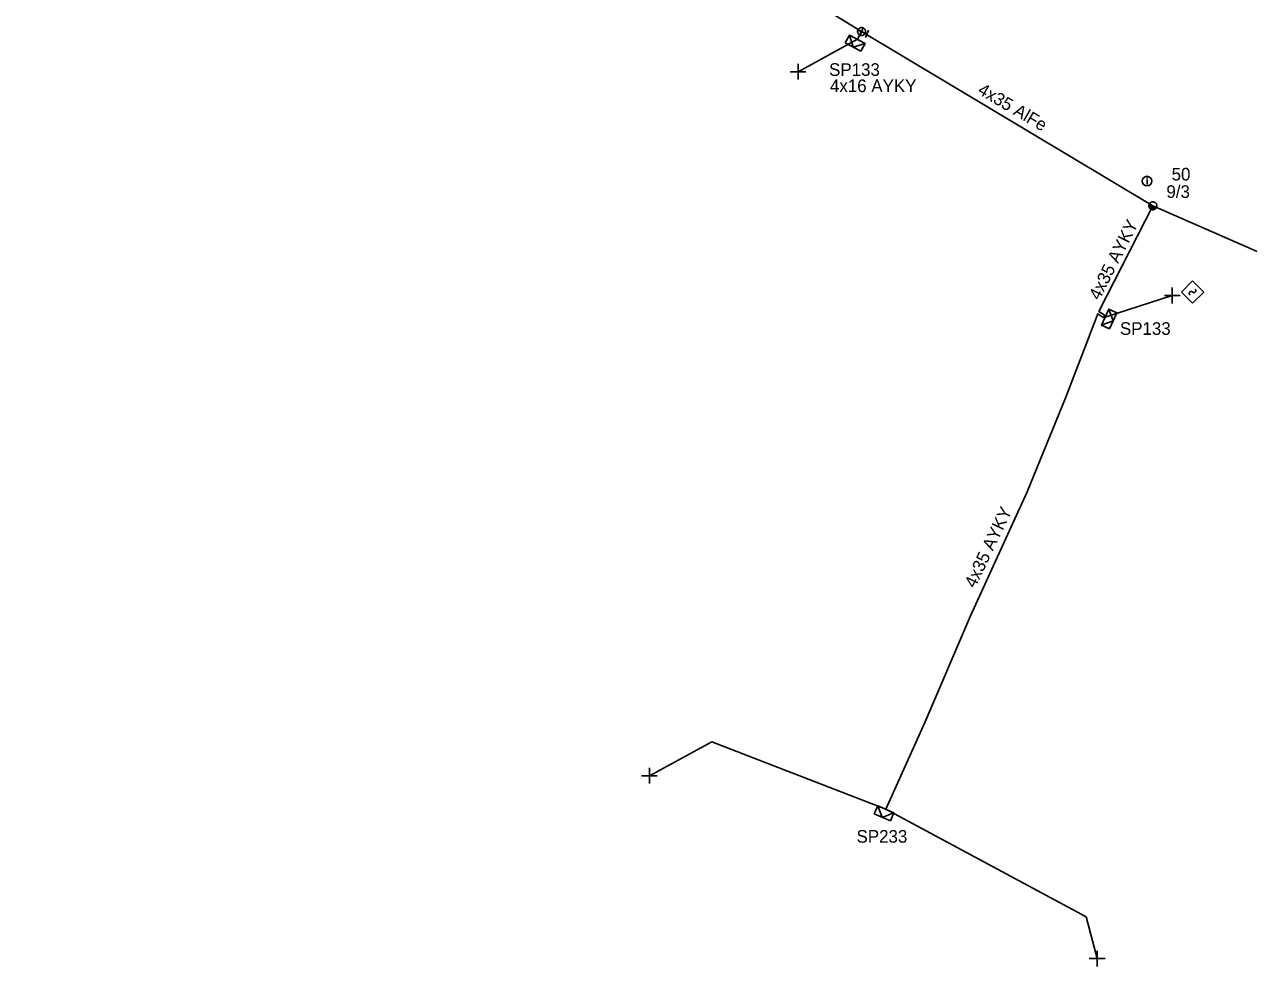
# Model space of a CAD drawing. Extents: x -748492 to -735633, y -1146251 to -1139940.
# Drawn here: x -736671.1 to -736574.3, y -1143545.2 to -1143470.7 of the extents above; entities that cross this region are included whole.
import ezdxf

# ---------------------------------------------------------------- set-up
doc = ezdxf.new("R2010")
doc.units = 0
for name, color, linetype in [('Vrstva 1', 7, 'Continuous'), ('Vrstva 10', 7, 'Continuous'), ('Vrstva 12', 7, 'Continuous'), ('Vrstva 13', 7, 'Continuous'), ('Vrstva 14', 7, 'Continuous'), ('Vrstva 2', 7, 'Continuous'), ('Vrstva 31', 7, 'Continuous'), ('Vrstva 33', 7, 'Continuous'), ('Vrstva 34', 7, 'Continuous'), ('Vrstva 36', 7, 'Continuous'), ('Vrstva 5', 7, 'Continuous'), ('Vrstva 52', 7, 'Continuous'), ('Vrstva 54', 7, 'Continuous'), ('Vrstva 59', 7, 'Continuous'), ('Vrstva 6', 7, 'Continuous'), ('Vrstva 9', 7, 'Continuous')]:
    doc.layers.add(name, color=color, linetype=linetype)

# ---------------------------------------------------------------- blocks, each defined once
blk = doc.blocks.new('NN440')
at = {"layer": 'Vrstva 2'}
for points in [[(0.63, 0), (0.63, 0.06), (0.62, 0.13), (0.6, 0.19), (0.58, 0.25), (0.55, 0.31), (0.51, 0.37), (0.47, 0.42), (0.42, 0.46), (0.37, 0.51), (0.32, 0.54), (0.26, 0.57), (0.2, 0.59), (0.13, 0.61), (0.07, 0.62), (0, 0.63), (-0.06, 0.62), (-0.13, 0.61), (-0.19, 0.59), (-0.26, 0.57), (-0.31, 0.54), (-0.37, 0.51), (-0.42, 0.46), (-0.47, 0.42), (-0.51, 0.37), (-0.54, 0.31), (-0.57, 0.25), (-0.6, 0.19), (-0.62, 0.13), (-0.63, 0.06), (-0.63, 0), (-0.63, -0.07), (-0.62, -0.14), (-0.6, -0.2), (-0.57, -0.26), (-0.54, -0.32), (-0.51, -0.37), (-0.47, -0.43), (-0.42, -0.47), (-0.37, -0.51), (-0.31, -0.55), (-0.26, -0.58), (-0.19, -0.6), (-0.13, -0.62), (-0.06, -0.63), (0, -0.63), (0.07, -0.63), (0.13, -0.62), (0.2, -0.6), (0.26, -0.58), (0.32, -0.55), (0.37, -0.51), (0.42, -0.47), (0.47, -0.43), (0.51, -0.37), (0.55, -0.32), (0.58, -0.26), (0.6, -0.2), (0.62, -0.14), (0.63, -0.07), (0.63, 0)], [(-0.63, 0), (0.63, 0)], [(-0.6, -0.18), (0.57, -0.18)], [(-0.51, -0.32), (0.5, -0.32)], [(-0.37, -0.47), (0.35, -0.47)]]:
    blk.add_lwpolyline(points, dxfattribs=at)
blk = doc.blocks.new('NN770')
at = {"layer": 'Vrstva 10'}
for p, q in [((0.002, 0.187), (0.002, 0.263)), ((0.002, -0.276), (0.002, 0.111))]:
    blk.add_line(p, q, dxfattribs=at)
blk.add_circle((0, -0.008), 0.375, dxfattribs=at)
blk = doc.blocks.new('NN800')
at = {"layer": 'Vrstva 1'}
for points in [[(-0.442, 0.442), (0.442, -0.442)], [(-0.442, -0.442), (0.442, 0.442)]]:
    blk.add_lwpolyline(points, dxfattribs=at)
blk = doc.blocks.new('NN630')
at = {"layer": 'Vrstva 9'}
for points in [[(-0.003, -0.7), (-0.703, 0)], [(-0.703, -0.7), (-0.703, 0), (0.697, 0), (0.697, -0.7)], [(-0.703, -0.7), (0.697, -0.7)], [(-0.003, -0.7), (0.697, 0)]]:
    blk.add_lwpolyline(points, dxfattribs=at)
blk = doc.blocks.new('NN740')
at = {"layer": 'Vrstva 1'}
for points in [[(0.624, 0.624), (-0.626, 0.624)], [(-0.626, 0.624), (-0.626, -0.626)], [(-0.001, -0.001), (-0.002, 0.015), (-0.004, 0.031), (-0.008, 0.046), (-0.014, 0.061), (-0.021, 0.075), (-0.03, 0.089), (-0.04, 0.101), (-0.051, 0.112), (-0.063, 0.123), (-0.077, 0.131), (-0.091, 0.139), (-0.106, 0.145), (-0.121, 0.149), (-0.137, 0.151), (-0.153, 0.152), (-0.169, 0.151), (-0.185, 0.149), (-0.2, 0.145), (-0.215, 0.139), (-0.229, 0.132), (-0.243, 0.123), (-0.255, 0.113), (-0.266, 0.102), (-0.276, 0.09), (-0.285, 0.076), (-0.293, 0.062), (-0.298, 0.047), (-0.303, 0.032), (-0.305, 0.016), (-0.306, 0), (-0.306, -0.001)], [(0.624, -0.626), (0.624, 0.624)], [(-0.626, -0.626), (0.624, -0.626)], [(-0.001, -0.001), (0, -0.017), (0.002, -0.032), (0.006, -0.048), (0.011, -0.062), (0.018, -0.077), (0.026, -0.09), (0.036, -0.102), (0.047, -0.114), (0.059, -0.124), (0.072, -0.133), (0.085, -0.14), (0.1, -0.146), (0.115, -0.15), (0.131, -0.153), (0.146, -0.154), (0.162, -0.154), (0.178, -0.151), (0.193, -0.148), (0.208, -0.142), (0.222, -0.135), (0.235, -0.127), (0.247, -0.118), (0.259, -0.107), (0.269, -0.095), (0.278, -0.082), (0.285, -0.068), (0.291, -0.053), (0.295, -0.038), (0.298, -0.023), (0.299, -0.007), (0.299, -0.006)]]:
    blk.add_lwpolyline(points, dxfattribs=at)
blk = doc.blocks.new('NN410')
at = {"layer": 'Vrstva 2'}
for points in [[(0.01, 0.63), (-0.06, 0.63), (-0.13, 0.62), (-0.19, 0.6), (-0.25, 0.58), (-0.31, 0.55), (-0.37, 0.51), (-0.42, 0.47), (-0.46, 0.42), (-0.5, 0.37), (-0.54, 0.32), (-0.57, 0.26), (-0.59, 0.2), (-0.61, 0.13), (-0.62, 0.07), (-0.62, 0), (-0.62, -0.06), (-0.61, -0.13), (-0.59, -0.19), (-0.57, -0.25), (-0.54, -0.31), (-0.5, -0.37), (-0.46, -0.42), (-0.42, -0.47), (-0.37, -0.51), (-0.31, -0.54), (-0.25, -0.57), (-0.19, -0.6), (-0.13, -0.61), (-0.06, -0.62), (0.01, -0.63), (0.07, -0.62), (0.14, -0.61), (0.2, -0.6), (0.26, -0.57), (0.32, -0.54), (0.38, -0.51), (0.43, -0.47), (0.47, -0.42), (0.51, -0.37), (0.55, -0.31), (0.58, -0.25), (0.6, -0.19), (0.62, -0.13), (0.63, -0.06), (0.63, 0), (0.63, 0.07), (0.62, 0.13), (0.6, 0.2), (0.58, 0.26), (0.55, 0.32), (0.51, 0.37), (0.47, 0.42), (0.43, 0.47), (0.38, 0.51), (0.32, 0.55), (0.26, 0.58), (0.2, 0.6), (0.14, 0.62), (0.07, 0.63), (0.01, 0.63)], [(0, -0.63), (0, 0.63)], [(0.96, -0.63), (0.96, 0.63)], [(-0.63, 0), (0.63, 0)]]:
    blk.add_lwpolyline(points, dxfattribs=at)

msp = doc.modelspace()

# ---------------------------------------------------------------- linework, layer by layer
at = {"layer": 'Vrstva 1'}
for points in [[(-736676.261, -1143404.169), (-736662.23, -1143427.97), (-736645.42, -1143442.01), (-736626.46, -1143458.019), (-736604.89, -1143471.26), (-736581.85, -1143485.04)], [(-736581.85, -1143485.04), (-736559.03, -1143495.02), (-736543, -1143503.11), (-736522.07, -1143513.24)]]:
    msp.add_lwpolyline(points, dxfattribs=at)
at = {"layer": 'Vrstva 5'}
msp.add_lwpolyline([(-736581.85, -1143485.04), (-736586.114, -1143493.39), (-736585.706, -1143493.663), (-736585.62, -1143493.84)], dxfattribs=at)
at = {"layer": 'Vrstva 52'}
for points in [[(-736604.89, -1143471.26), (-736605.221, -1143471.872)], [(-736585.62, -1143493.84), (-736585.808, -1143493.835), (-736586.197, -1143493.576), (-736588.74, -1143500.17), (-736591.79, -1143507.66), (-736596.28, -1143517.47), (-736599.88, -1143525.89), (-736602.96, -1143532.76)]]:
    msp.add_lwpolyline(points, dxfattribs=at)
at = {"layer": 'Vrstva 59'}
for points in [[(-736605.221, -1143471.872), (-736609.912, -1143474.433)], [(-736585.62, -1143493.84), (-736580.314, -1143492.136)], [(-736602.96, -1143532.76), (-736616.74, -1143527.413), (-736621.667, -1143530.104)], [(-736602.96, -1143532.76), (-736587.137, -1143541.269), (-736586.251, -1143544.567)]]:
    msp.add_lwpolyline(points, dxfattribs=at)

# ---------------------------------------------------------------- block references
at = {"layer": 'Vrstva 13'}
for name, p, xscale, yscale, rotation in [('NN410', (-736604.89, -1143471.26), 0.49999999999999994, 0.5000000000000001, -21.950945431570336), ('NN440', (-736581.85, -1143485.04), 0.5000000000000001, 0.4999999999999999, -22.701708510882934)]:
    msp.add_blockref(name, p, dxfattribs=dict(at, xscale=xscale, yscale=yscale, rotation=rotation))
at = {"layer": 'Vrstva 31'}
for p, rotation in [((-736605.221, -1143471.872), -28.231918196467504), ((-736585.62, -1143493.84), 65.75311860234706), ((-736602.96, -1143532.76), -24.06667780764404)]:
    msp.add_blockref('NN630', p, dxfattribs=dict(at, rotation=rotation))
at = {"layer": 'Vrstva 34'}
for name, p, rotation in [('NN800', (-736609.912, -1143474.433), 45), ('NN740', (-736578.712, -1143491.86), 45), ('NN800', (-736580.314, -1143492.136), 45.00000009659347), ('NN800', (-736621.667, -1143530.104), 45), ('NN800', (-736586.251, -1143544.567), 45)]:
    msp.add_blockref(name, p, dxfattribs=dict(at, rotation=rotation))
at = {"layer": 'Vrstva 36'}
msp.add_blockref('NN770', (-736582.315, -1143483.073), dxfattribs=at)

# ---------------------------------------------------------------- texts
at = {"layer": 'Vrstva 12'}
msp.add_text('9/3', height=1, dxfattribs=at).set_placement((-736580.78, -1143484.416))
at = {"layer": 'Vrstva 14'}
msp.add_text('50', height=1, dxfattribs=at).set_placement((-736580.368, -1143483.038))
at = {"layer": 'Vrstva 2'}
msp.add_text('4x35 AlFe', height=1, rotation=329.576, dxfattribs=at).set_placement((-736595.784, -1143476.133))
at = {"layer": 'Vrstva 33'}
for s, p in [('SP133', (-736607.454, -1143474.767)), ('SP133', (-736584.457, -1143495.245)), ('SP233', (-736605.285, -1143535.4))]:
    msp.add_text(s, height=1, dxfattribs=at).set_placement(p)
at = {"layer": 'Vrstva 54'}
msp.add_text('4x16 AYKY', height=1, dxfattribs=at).set_placement((-736607.386, -1143476.05))
msp.add_text('4x35 AYKY', height=1, rotation=64.47, dxfattribs=at).set_placement((-736595.908, -1143515.329))
at = {"layer": 'Vrstva 6'}
msp.add_text('4x35 AYKY', height=1, rotation=63.08, dxfattribs=at).set_placement((-736586.08, -1143492.569))

doc.saveas('drawing.dxf')
